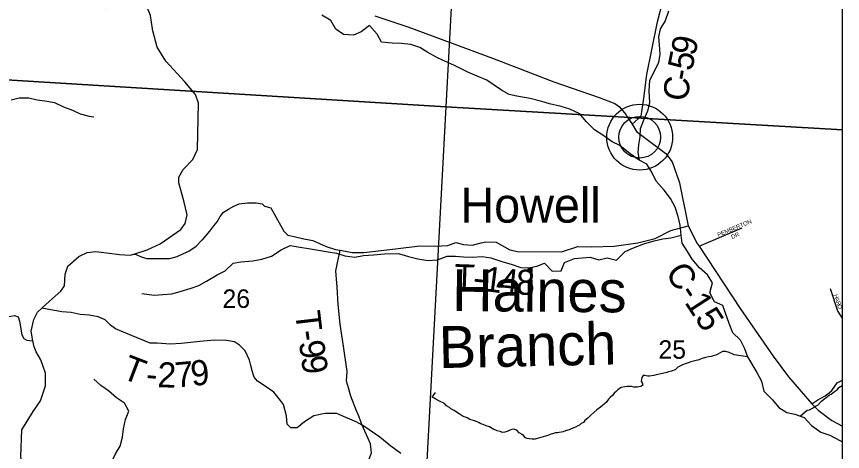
# Model space of a CAD drawing. Extents: x 1949938.81 to 1949945.61, y 152207.65 to 152214.09.
# Drawn here: x 1949943.741 to 1949945.607, y 152210.239 to 152211.223 of the extents above; entities that cross this region are included whole.
import ezdxf

# ---------------------------------------------------------------- set-up
doc = ezdxf.new("R2010")
doc.units = 0
for name, color, linetype in [('GM_X_County', 7, 'Continuous'), ('GM_X_County_Road', 7, 'Continuous'), ('GM_X_County_Road_Text', 7, 'Continuous'), ('GM_X_Minor_River', 7, 'Continuous'), ('GM_X_Minor_River_Text', 7, 'Continuous'), ('GM_X_Section', 7, 'Continuous'), ('GM_X_Section_Text', 7, 'Continuous'), ('GM_X_Township', 7, 'Continuous'), ('GM_X_Township_Road', 7, 'Continuous'), ('GM_X_Township_Road_Text', 7, 'Continuous'), ('GM_X_Township_ROW', 7, 'Continuous'), ('GM_X_Township_Subdivision', 7, 'Continuous'), ('GM_X_Township_Subdivision_Text', 7, 'Continuous'), ('GM_X_Unincorporated', 7, 'Continuous'), ('GM_X_Unincorporated_Location', 7, 'Continuous'), ('GM_X_Unincorporated_Text', 7, 'Continuous')]:
    doc.layers.add(name, color=color, linetype=linetype)

msp = doc.modelspace()

# ---------------------------------------------------------------- linework, layer by layer
at = {"layer": 'GM_X_County'}
msp.add_lwpolyline([(1949945.6069, 152208.8266), (1949945.6069, 152214.0874), (1949938.8069, 152214.0874), (1949938.8069, 152213.1813)], dxfattribs=at)
at = {"layer": 'GM_X_County_Road'}
for points in [[(1949944.0481, 152211.1938), (1949944.0481, 152211.1943), (1949944.0437, 152211.2246), (1949944.0338, 152211.2489), (1949944.0225, 152211.2546), (1949943.9414, 152211.2402), (1949943.9251, 152211.2417), (1949943.9054, 152211.2535), (1949943.863, 152211.3067), (1949943.8501, 152211.3154), (1949943.8244, 152211.328), (1949943.7793, 152211.3512), (1949943.749, 152211.3766), (1949943.6543, 152211.5096), (1949943.6025, 152211.5897), (1949943.5635, 152211.6585), (1949943.5517, 152211.6824), (1949943.5415, 152211.7117), (1949943.5373, 152211.7447), (1949943.5305, 152211.769)], [(1949945.1315, 152210.9793), (1949945.1517, 152210.9974), (1949945.1582, 152211.038), (1949945.1647, 152211.0916), (1949945.176, 152211.1468), (1949945.189, 152211.2101), (1949945.2003, 152211.2539)], [(1949944.5506, 152211.224), (1949944.6249, 152211.1992), (1949944.8162, 152211.1283), (1949944.9544, 152211.0751), (1949945.0571, 152211.0396), (1949945.0925, 152211.0254), (1949945.1032, 152211.0184), (1949945.1173, 152211.0006), (1949945.1206, 152210.9957), (1949945.1315, 152210.9793), (1949945.1415, 152210.9627), (1949945.2077, 152210.9129), (1949945.2219, 152210.894), (1949945.2362, 152210.8531), (1949945.2384, 152210.8466), (1949945.2579, 152210.7491)], [(1949943.7778, 152210.4892), (1949943.7736, 152210.5111), (1949943.7801, 152210.5373), (1949943.788, 152210.5537), (1949943.7981, 152210.5629), (1949943.8149, 152210.5784), (1949943.8407, 152210.6012), (1949943.849, 152210.613), (1949943.8509, 152210.64), (1949943.8566, 152210.6575), (1949943.8812, 152210.6795), (1949943.9005, 152210.6886), (1949943.9198, 152210.6913), (1949943.9501, 152210.6871), (1949943.9732, 152210.684), (1949943.9975, 152210.6825), (1949944.0061, 152210.6852), (1949944.0361, 152210.6947), (1949944.0653, 152210.7087), (1949944.1119, 152210.7407), (1949944.1217, 152210.7543), (1949944.1263, 152210.7737), (1949944.1187, 152210.8057), (1949944.1073, 152210.846), (1949944.1077, 152210.8593), (1949944.1175, 152210.8768), (1949944.1391, 152210.8992), (1949944.1494, 152210.9216), (1949944.152, 152211.0262), (1949944.1452, 152211.0463), (1949944.1206, 152211.0748), (1949944.0778, 152211.1212), (1949944.0585, 152211.1535), (1949944.0486, 152211.1904), (1949944.0481, 152211.1938)], [(1949945.2579, 152210.7491), (1949945.2787, 152210.7093), (1949945.2828, 152210.7031), (1949945.3756, 152210.5624), (1949945.4501, 152210.4546), (1949945.4851, 152210.4079), (1949945.5376, 152210.3464), (1949945.5517, 152210.332), (1949945.5828, 152210.3085), (1949945.6069, 152210.2963)], [(1949943.207, 152210.6254), (1949943.2969, 152210.625), (1949943.3279, 152210.6214), (1949943.344, 152210.6195), (1949943.405, 152210.6001), (1949943.5201, 152210.5515), (1949943.5506, 152210.539), (1949943.5894, 152210.5306), (1949943.6601, 152210.532), (1949943.7114, 152210.5418), (1949943.728, 152210.5445), (1949943.7364, 152210.5459), (1949943.7447, 152210.5431), (1949943.7474, 152210.5334), (1949943.753, 152210.5029), (1949943.7572, 152210.4945), (1949943.7641, 152210.4904), (1949943.7778, 152210.4892)], [(1949943.7934, 152210.0582), (1949943.7863, 152210.0783), (1949943.778, 152210.1014), (1949943.7733, 152210.1163), (1949943.7689, 152210.1332), (1949943.7647, 152210.1506), (1949943.7587, 152210.1777), (1949943.7547, 152210.198), (1949943.7505, 152210.2272), (1949943.7528, 152210.2879), (1949943.7786, 152210.3293), (1949943.7948, 152210.3533), (1949943.8062, 152210.3875), (1949943.8062, 152210.4156), (1949943.7956, 152210.4457), (1949943.785, 152210.4643), (1949943.7804, 152210.4757), (1949943.7778, 152210.4892)]]:
    msp.add_lwpolyline(points, dxfattribs=at)
at = {"layer": 'GM_X_Minor_River'}
for points in [[(1949945.214, 152211.2348), (1949945.2063, 152211.2128), (1949945.1949, 152211.1946), (1949945.191, 152211.1764), (1949945.1925, 152211.1581), (1949945.1939, 152211.1376), (1949945.1915, 152211.1186), (1949945.1831, 152211.1012), (1949945.1709, 152211.0777), (1949945.1693, 152211.0541), (1949945.1707, 152211.0282), (1949945.1661, 152211.0085), (1949945.1577, 152210.9895), (1949945.15, 152210.9683), (1949945.1492, 152210.95), (1949945.1461, 152210.9325), (1949945.1445, 152210.915), (1949945.1475, 152210.8975)], [(1949945.3758, 152210.4911), (1949945.3588, 152210.5073), (1949945.3505, 152210.5278), (1949945.3423, 152210.5515), (1949945.3363, 152210.569), (1949945.3174, 152210.5774), (1949945.3069, 152210.5972), (1949945.313, 152210.6201), (1949945.3017, 152210.6384), (1949945.2836, 152210.6544), (1949945.267, 152210.6735), (1949945.2565, 152210.691), (1949945.2445, 152210.7101), (1949945.2422, 152210.7276), (1949945.2401, 152210.7504), (1949945.2356, 152210.7702), (1949945.2289, 152210.7915), (1949945.2183, 152210.8106), (1949945.204, 152210.8296), (1949945.1859, 152210.8503), (1949945.1762, 152210.8701), (1949945.1649, 152210.8884), (1949945.1475, 152210.8975), (1949945.1271, 152210.9121), (1949945.1037, 152210.9304), (1949945.0863, 152210.9388), (1949945.0652, 152210.9541), (1949945.0463, 152210.9663), (1949945.0274, 152210.9847), (1949945.0131, 152211.0022), (1949944.9912, 152211.0129), (1949944.9715, 152211.0191), (1949944.945, 152211.0253), (1949944.9276, 152211.0299), (1949944.9012, 152211.0368), (1949944.8709, 152211.0423), (1949944.8535, 152211.0461), (1949944.8361, 152211.0561), (1949944.8036, 152211.0782), (1949944.7817, 152211.0874), (1949944.7605, 152211.0966), (1949944.7303, 152211.1119), (1949944.7099, 152211.1204), (1949944.6917, 152211.1288), (1949944.6698, 152211.141), (1949944.6517, 152211.1525), (1949944.6313, 152211.1594), (1949944.6108, 152211.1618), (1949944.5896, 152211.1619), (1949944.5654, 152211.1642), (1949944.5556, 152211.1825), (1949944.5383, 152211.2023), (1949944.5193, 152211.1879), (1949944.5019, 152211.1804), (1949944.4791, 152211.182), (1949944.4618, 152211.1935), (1949944.4512, 152211.2133), (1949944.4308, 152211.2255)], [(1949943.7288, 152211.0341), (1949943.747, 152211.0386), (1949943.7682, 152211.0385), (1949943.7871, 152211.0339), (1949943.8045, 152211.0316), (1949943.8264, 152211.0277), (1949943.8469, 152211.0185), (1949943.8673, 152211.0108), (1949943.8847, 152211.0024), (1949943.9051, 152210.997), (1949943.9157, 152210.9955)], [(1949944.0239, 152210.5958), (1949944.0519, 152210.5919), (1949944.0709, 152210.5934), (1949944.0913, 152210.5956), (1949944.1103, 152210.6008), (1949944.1353, 152210.6084), (1949944.1527, 152210.6144), (1949944.1702, 152210.6242), (1949944.1937, 152210.6386), (1949944.2119, 152210.6476), (1949944.2302, 152210.6643), (1949944.2476, 152210.668), (1949944.2749, 152210.6702), (1949944.2953, 152210.674), (1949944.3166, 152210.6807), (1949944.3386, 152210.6951), (1949944.3591, 152210.7049), (1949944.4227, 152210.694), (1949944.4446, 152210.6902), (1949944.4635, 152210.6871), (1949944.4824, 152210.6809), (1949944.5052, 152210.6785), (1949944.5249, 152210.6823), (1949944.5476, 152210.6837), (1949944.5718, 152210.6859), (1949944.6036, 152210.6865), (1949944.6263, 152210.6796), (1949944.6475, 152210.6742), (1949944.6702, 152210.6703), (1949944.6922, 152210.6718), (1949944.7134, 152210.6808), (1949944.7324, 152210.6808), (1949944.7505, 152210.6792), (1949944.771, 152210.6783), (1949944.793, 152210.6798), (1949944.8126, 152210.6767), (1949944.8391, 152210.6674), (1949944.858, 152210.662), (1949944.88, 152210.6551), (1949944.8974, 152210.6543), (1949944.9163, 152210.658), (1949944.9338, 152210.6648), (1949944.9511, 152210.6465), (1949944.9716, 152210.6472), (1949944.9785, 152210.6662), (1949945.0012, 152210.6752), (1949945.0186, 152210.6767), (1949945.0368, 152210.6781), (1949945.0565, 152210.672), (1949945.0754, 152210.6765), (1949945.0966, 152210.6711), (1949945.1156, 152210.6908), (1949945.1346, 152210.6991), (1949945.1581, 152210.7081), (1949945.1816, 152210.7149), (1949945.2006, 152210.7194), (1949945.2188, 152210.7223), (1949945.2422, 152210.7276), (1949945.2407, 152210.7268)], [(1949945.3758, 152210.4911), (1949945.3853, 152210.4714), (1949945.3921, 152210.4524), (1949945.4132, 152210.4174), (1949945.4238, 152210.3976), (1949945.429, 152210.3748), (1949945.4487, 152210.3557), (1949945.4631, 152210.3382), (1949945.4812, 152210.3268), (1949945.4994, 152210.323), (1949945.5206, 152210.3154), (1949945.5372, 152210.2971), (1949945.5576, 152210.2827), (1949945.5781, 152210.2758), (1949945.6023, 152210.2629), (1949945.6069, 152210.2602)], [(1949945.3921, 152210.4524), (1949945.3622, 152210.4575), (1949945.3588, 152210.4587), (1949945.3509, 152210.4623), (1949945.3433, 152210.4647), (1949945.3358, 152210.4645), (1949945.3254, 152210.4585), (1949945.3209, 152210.4567), (1949945.3148, 152210.4553), (1949945.3098, 152210.4539), (1949945.3041, 152210.4524), (1949945.2973, 152210.451), (1949945.29, 152210.4489), (1949945.2859, 152210.4478), (1949945.2798, 152210.4456), (1949945.276, 152210.4442), (1949945.2702, 152210.4431), (1949945.2642, 152210.4413), (1949945.2604, 152210.4402), (1949945.2535, 152210.4377), (1949945.2451, 152210.4344), (1949945.2352, 152210.4296), (1949945.2286, 152210.4233), (1949945.2202, 152210.4204), (1949945.2141, 152210.4186), (1949945.21, 152210.4171), (1949945.2005, 152210.4154), (1949945.1963, 152210.4143), (1949945.1898, 152210.4129), (1949945.1856, 152210.4118), (1949945.1807, 152210.4108), (1949945.1708, 152210.409), (1949945.167, 152210.4091), (1949945.1636, 152210.4095), (1949945.1602, 152210.4104), (1949945.1568, 152210.4104), (1949945.1537, 152210.4063), (1949945.1525, 152210.4021), (1949945.1517, 152210.3979), (1949945.1542, 152210.3937), (1949945.1557, 152210.3887), (1949945.1511, 152210.3858), (1949945.1469, 152210.3847), (1949945.1427, 152210.3844), (1949945.1355, 152210.3845), (1949945.1302, 152210.3854), (1949945.1261, 152210.3858), (1949945.12, 152210.3859), (1949945.1151, 152210.3852), (1949945.1067, 152210.3835), (1949945.1029, 152210.3813), (1949945.0994, 152210.3783), (1949945.0952, 152210.3742), (1949945.091, 152210.3708), (1949945.0879, 152210.3659), (1949945.0817, 152210.3611), (1949945.0782, 152210.3569), (1949945.0732, 152210.3494), (1949945.0601, 152210.339), (1949945.0521, 152210.333), (1949945.0452, 152210.3271), (1949945.0386, 152210.3207), (1949945.0313, 152210.3144), (1949945.0251, 152210.3087), (1949945.0217, 152210.3046), (1949945.0163, 152210.3017), (1949945.0125, 152210.2983), (1949945.0086, 152210.2968), (1949945.004, 152210.2935), (1949945.0002, 152210.292), (1949944.9938, 152210.2902), (1949944.9895, 152210.2877), (1949944.9808, 152210.2855), (1949944.9758, 152210.2833), (1949944.9671, 152210.2816), (1949944.9629, 152210.2809), (1949944.9584, 152210.2806), (1949944.9519, 152210.2788), (1949944.9481, 152210.2777), (1949944.9447, 152210.2766), (1949944.9408, 152210.2748), (1949944.9256, 152210.2705), (1949944.9222, 152210.2698), (1949944.9169, 152210.2683), (1949944.9127, 152210.2669), (1949944.9055, 152210.2666), (1949944.899, 152210.2671), (1949944.8945, 152210.268), (1949944.8904, 152210.2699), (1949944.8863, 152210.2746), (1949944.8829, 152210.2769), (1949944.8766, 152210.2812), (1949944.8714, 152210.287), (1949944.8646, 152210.2894), (1949944.8596, 152210.2884), (1949944.8555, 152210.2869), (1949944.849, 152210.284), (1949944.8436, 152210.2822), (1949944.8387, 152210.2819), (1949944.8331, 152210.2839), (1949944.827, 152210.2855)], [(1949943.9548, 152210.1617), (1949943.9541, 152210.1868), (1949943.9542, 152210.2134), (1949943.9642, 152210.2332), (1949943.9748, 152210.2506), (1949943.9802, 152210.2712), (1949943.9826, 152210.2902), (1949943.9872, 152210.3114), (1949943.9941, 152210.3297), (1949943.9843, 152210.348), (1949943.9669, 152210.3602), (1949943.9488, 152210.3762), (1949943.9315, 152210.3877), (1949943.9156, 152210.4022)], [(1949945.5116, 152210.3189), (1949945.5224, 152210.3284), (1949945.5274, 152210.3322), (1949945.5324, 152210.3332), (1949945.5392, 152210.3365), (1949945.5461, 152210.341), (1949945.5511, 152210.3432), (1949945.5592, 152210.3522), (1949945.568, 152210.3592), (1949945.5719, 152210.3626), (1949945.5773, 152210.3671), (1949945.5811, 152210.3685), (1949945.5891, 152210.3741), (1949945.5953, 152210.379), (1949945.5987, 152210.3831), (1949945.606, 152210.3883), (1949945.6069, 152210.389)], [(1949944.827, 152210.2855), (1949944.8236, 152210.2871), (1949944.8191, 152210.2887), (1949944.8154, 152210.291), (1949944.8094, 152210.2945), (1949944.8018, 152210.2969), (1949944.7947, 152210.2997), (1949944.7898, 152210.3013), (1949944.786, 152210.3037), (1949944.7812, 152210.3057), (1949944.7755, 152210.3077), (1949944.765, 152210.3109), (1949944.759, 152210.3148), (1949944.7552, 152210.316), (1949944.7518, 152210.3172), (1949944.7477, 152210.3196), (1949944.7406, 152210.3239), (1949944.7372, 152210.3258), (1949944.7297, 152210.3317), (1949944.7222, 152210.3348), (1949944.7188, 152210.3383), (1949944.7121, 152210.3422), (1949944.7076, 152210.3469), (1949944.6952, 152210.3532), (1949944.6877, 152210.3567), (1949944.684, 152210.3591), (1949944.6799, 152210.3614), (1949944.6876, 152210.372)]]:
    msp.add_lwpolyline(points, dxfattribs=at)
at = {"layer": 'GM_X_Section'}
for p, q in [((1949945.6069, 152210.9665), (1949945.6069, 152211.9807)), ((1949945.6069, 152209.9543), (1949945.6069, 152210.9665))]:
    msp.add_line(p, q, dxfattribs=at)
for points in [[(1949943.6665, 152212.0918), (1949944.7648, 152212.0263), (1949944.7104, 152211.0185), (1949943.6063, 152211.0859)], [(1949944.7104, 152211.0185), (1949944.6567, 152210.0065), (1949943.5439, 152210.0754), (1949943.6063, 152211.0859)]]:
    msp.add_lwpolyline(points, close=True, dxfattribs=at)
for points in [[(1949945.6069, 152211.9807), (1949944.7648, 152212.0263), (1949944.7104, 152211.0185), (1949945.6069, 152210.9665)], [(1949945.6069, 152210.9665), (1949944.7104, 152211.0185), (1949944.6567, 152210.0065), (1949945.6069, 152209.9543)]]:
    msp.add_lwpolyline(points, dxfattribs=at)
at = {"layer": 'GM_X_Township'}
msp.add_lwpolyline([(1949945.6069, 152208.8266), (1949945.6069, 152214.0874), (1949942.6839, 152214.0874)], dxfattribs=at)
at = {"layer": 'GM_X_Township_Road'}
for points in [[(1949944.5971, 152210.6972), (1949944.652, 152210.7039), (1949944.6865, 152210.7032), (1949944.7149, 152210.7043), (1949944.7331, 152210.7111), (1949944.7509, 152210.7069), (1949944.7698, 152210.705), (1949944.7906, 152210.7103), (1949944.8012, 152210.713), (1949944.8247, 152210.7122), (1949944.855, 152210.6947), (1949944.8725, 152210.6909), (1949944.9717, 152210.6905), (1949945.0088, 152210.7026), (1949945.0403, 152210.7015), (1949945.091, 152210.703), (1949945.1444, 152210.7109), (1949945.1834, 152210.7204), (1949945.2187, 152210.7383), (1949945.2579, 152210.7491)], [(1949944.5145, 152210.3167), (1949944.5092, 152210.3308), (1949944.4963, 152210.3639), (1949944.4907, 152210.383), (1949944.4865, 152210.3978), (1949944.4876, 152210.4199), (1949944.4793, 152210.4769), (1949944.4721, 152210.5264), (1949944.4672, 152210.5709), (1949944.4649, 152210.6101), (1949944.4622, 152210.647), (1949944.4717, 152210.6937)], [(1949944.2723, 152210.4247), (1949944.2698, 152210.4329), (1949944.2672, 152210.4455), (1949944.2573, 152210.466), (1949944.2445, 152210.4793), (1949944.2335, 152210.4869), (1949944.2149, 152210.49), (1949944.188, 152210.4904), (1949944.1551, 152210.4877), (1949944.1346, 152210.4855), (1949944.113, 152210.4828), (1949944.0876, 152210.4817), (1949944.0581, 152210.4836), (1949944.0429, 152210.4836), (1949944.0005, 152210.5011), (1949943.9823, 152210.5083), (1949943.9645, 152210.5163), (1949943.9528, 152210.5247), (1949943.9407, 152210.5361), (1949943.9248, 152210.543), (1949943.9047, 152210.5468), (1949943.8846, 152210.5487), (1949943.8638, 152210.5533), (1949943.8429, 152210.5544), (1949943.7981, 152210.5629)], [(1949945.5376, 152210.3464), (1949945.5509, 152210.3552), (1949945.5679, 152210.3647), (1949945.5766, 152210.3712), (1949945.583, 152210.3765), (1949945.5947, 152210.3941), (1949945.6069, 152210.4)], [(1949944.5236, 152210.2032), (1949944.5237, 152210.2034), (1949944.5361, 152210.2175), (1949944.543, 152210.2353), (1949944.5403, 152210.2559), (1949944.5215, 152210.2984), (1949944.5147, 152210.3164), (1949944.5145, 152210.3167)]]:
    msp.add_lwpolyline(points, dxfattribs=at)
at = {"layer": 'GM_X_Township_ROW'}
for points in [[(1949944.0061, 152210.6852), (1949944.011, 152210.6844), (1949944.0205, 152210.6796), (1949944.0347, 152210.6749), (1949944.087, 152210.6749), (1949944.1036, 152210.6796), (1949944.1179, 152210.6868), (1949944.1298, 152210.6915), (1949944.1464, 152210.7034), (1949944.1596, 152210.7166), (1949944.1606, 152210.7177), (1949944.1773, 152210.7368), (1949944.1868, 152210.7487), (1949944.1939, 152210.7582), (1949944.201, 152210.7701), (1949944.2081, 152210.7796), (1949944.22, 152210.7867), (1949944.2319, 152210.7939), (1949944.2438, 152210.7986), (1949944.2628, 152210.801), (1949944.2731, 152210.801)], [(1949944.2731, 152210.801), (1949944.2818, 152210.801), (1949944.296, 152210.7986), (1949944.3008, 152210.7939), (1949944.3156, 152210.7896), (1949944.3338, 152210.7558), (1949944.3444, 152210.7368), (1949944.3539, 152210.7276), (1949944.3679, 152210.7246), (1949944.3895, 152210.72), (1949944.41, 152210.7158), (1949944.4403, 152210.7025), (1949944.4615, 152210.6956), (1949944.4717, 152210.6937), (1949944.4994, 152210.6884), (1949944.5251, 152210.6884), (1949944.5971, 152210.6972)], [(1949944.6089, 152210.2338), (1949944.5861, 152210.2509), (1949944.5619, 152210.2711), (1949944.5251, 152210.2962), (1949944.5215, 152210.2984), (1949944.5081, 152210.3061), (1949944.485, 152210.3153), (1949944.4645, 152210.3248), (1949944.4384, 152210.3248), (1949944.4123, 152210.3191), (1949944.3914, 152210.3054), (1949944.3831, 152210.2993), (1949944.3748, 152210.2925), (1949944.3608, 152210.2921), (1949944.352, 152210.3005), (1949944.3505, 152210.3195), (1949944.3441, 152210.3446), (1949944.3373, 152210.3541), (1949944.3217, 152210.3732), (1949944.3005, 152210.388), (1949944.2854, 152210.3979), (1949944.2778, 152210.4067), (1949944.2727, 152210.4235), (1949944.2723, 152210.4247)]]:
    msp.add_lwpolyline(points, dxfattribs=at)
at = {"layer": 'GM_X_Township_Subdivision'}
for points in [[(1949945.2828, 152210.7031), (1949945.38, 152210.7445)], [(1949945.5993, 152210.5519), (1949945.5991, 152210.5522), (1949945.5966, 152210.5561), (1949945.5797, 152210.6068)], [(1949945.6069, 152210.5404), (1949945.5993, 152210.5519)]]:
    msp.add_lwpolyline(points, dxfattribs=at)
at = {"layer": 'GM_X_Unincorporated'}
for radius in [0.0744, 0.0472]:
    msp.add_circle((1949945.1487, 152210.9495), radius, dxfattribs=at)
at = {"layer": 'GM_X_Unincorporated_Location'}
msp.add_line((1949945.1487, 152210.9495), (1949945.1487, 152210.9495), dxfattribs=at)

# ---------------------------------------------------------------- texts
at = {"layer": 'GM_X_County_Road_Text'}
for s, height, rotation, p in [('9', 0.0568, 78.1389, (1949945.2738, 152211.1314)), ('5', 0.0568, 78.5958, (1949945.2669, 152211.0972)), ('C', 0.0568, 82.2918, (1949945.2567, 152211.0289)), ('-', 0.0568, 79.7983, (1949945.2628, 152211.0745)), ('C-15', 0.05682, 303.0238, (1949945.205, 152210.6433))]:
    msp.add_text(s, height=height, rotation=rotation, dxfattribs=at).set_placement(p)
at = {"layer": 'GM_X_Minor_River_Text'}
for s, rotation, p in [('Haines', 359.5508, (1949944.7247, 152210.5563)), ('Branch', 1.2147, (1949944.6957, 152210.4272))]:
    msp.add_text(s, height=0.09469, rotation=rotation, dxfattribs=at).set_placement(p)
at = {"layer": 'GM_X_Section_Text'}
for s, p in [('26', (1949944.2061, 152210.5634)), ('25', (1949945.1911, 152210.4484))]:
    msp.add_text(s, height=0.04186, rotation=0, dxfattribs=at).set_placement(p)
at = {"layer": 'GM_X_Township_Road_Text'}
for s, rotation, p in [('T', 357.9714, (1949944.7289, 152210.606)), ('1', 352.6917, (1949944.7932, 152210.6021)), ('4', 354.1461, (1949944.8295, 152210.5975)), ('8', 358.4968, (1949944.869, 152210.5936)), ('-', 353.7958, (1949944.7703, 152210.6046)), ('T', 276.6663, (1949944.3698, 152210.5539)), ('-', 277.9144, (1949944.3749, 152210.5103)), ('9', 278.4253, (1949944.3782, 152210.4866)), ('T', 339.0432, (1949943.9753, 152210.4054)), ('9', 277.9249, (1949944.3833, 152210.4522)), ('2', 358.1514, (1949944.0584, 152210.3842)), ('7', 5.1509, (1949944.101, 152210.3832)), ('9', 6.2418, (1949944.137, 152210.3865)), ('-', 355.0542, (1949944.0318, 152210.3864))]:
    msp.add_text(s, height=0.0568, rotation=rotation, dxfattribs=at).set_placement(p)
at = {"layer": 'GM_X_Township_Subdivision_Text'}
for s, rotation, p in [('PEMBERTON', 22.5671, (1949945.3263, 152210.7238)), ('DR', 23.9616, (1949945.3578, 152210.719)), ('H', 288.4342, (1949945.5867, 152210.5926)), ('A', 288.4342, (1949945.5894, 152210.5847)), ('R', 288.4342, (1949945.592, 152210.5768)), ('O', 291.1457, (1949945.5945, 152210.5692))]:
    msp.add_text(s, height=0.00947, rotation=rotation, dxfattribs=at).set_placement(p)
at = {"layer": 'GM_X_Unincorporated_Text'}
msp.add_text('Howell', height=0.07898, rotation=0, dxfattribs=at).set_placement((1949944.7436, 152210.7563))

doc.saveas('drawing.dxf')
